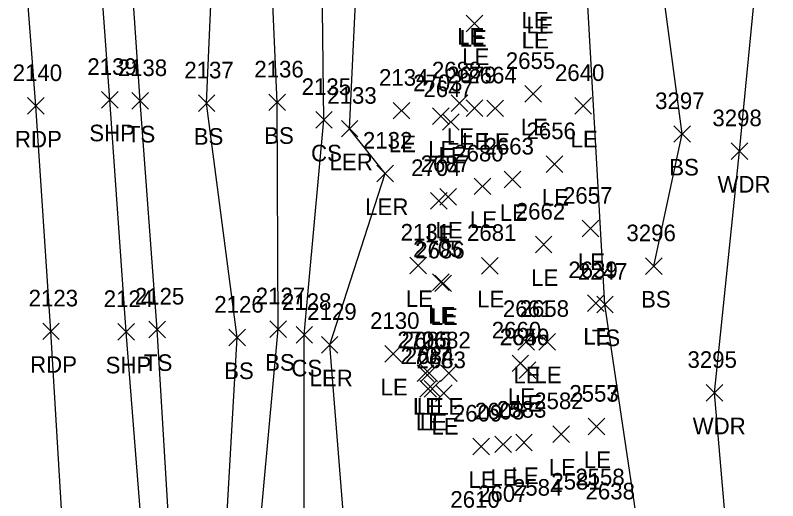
# Model space of a CAD drawing. Extents: x 1650221 to 1650634, y 244606 to 249996.
# Drawn here: x 1650384.9 to 1650476.7, y 246053.5 to 246112 of the extents above; entities that cross this region are included whole.
import ezdxf

# ---------------------------------------------------------------- set-up
doc = ezdxf.new("R2010")
doc.units = 0
for name, color, linetype in [('L_A', 7, 'Continuous'), ('L_I', 7, 'Continuous'), ('L_TIC', 7, 'Continuous'), ('LARO', 7, 'Continuous'), ('LAWA', 7, 'Continuous'), ('LELB', 7, 'Continuous'), ('P_A', 7, 'Continuous'), ('P_I', 7, 'Continuous'), ('P_TIC', 7, 'Continuous'), ('PET', 7, 'Continuous'), ('PSP', 7, 'Continuous')]:
    doc.layers.add(name, color=color, linetype=linetype)

msp = doc.modelspace()

# ---------------------------------------------------------------- linework, layer by layer
at = {"layer": 'L_TIC'}
for points in [[(1650439.182, 246110.018), (1650441.182, 246112.018)], [(1650441.182, 246110.018), (1650439.182, 246112.018)], [(1650446.244, 246101.548), (1650448.244, 246103.548)], [(1650448.244, 246101.548), (1650446.244, 246103.548)], [(1650398.903, 246100.695), (1650400.903, 246102.695)], [(1650400.903, 246100.695), (1650398.903, 246102.695)], [(1650406.916, 246100.417), (1650408.916, 246102.417)], [(1650408.916, 246100.417), (1650406.916, 246102.417)], [(1650415.402, 246100.528), (1650417.402, 246102.528)], [(1650417.402, 246100.528), (1650415.402, 246102.528)], [(1650437.343, 246100.414), (1650439.343, 246102.414)], [(1650439.343, 246100.414), (1650437.343, 246102.414)], [(1650430.36, 246099.524), (1650432.36, 246101.524)], [(1650432.36, 246099.524), (1650430.36, 246101.524)], [(1650439.182, 246099.825), (1650441.182, 246101.825)], [(1650441.182, 246099.825), (1650439.182, 246101.825)], [(1650441.655, 246099.809), (1650443.655, 246101.809)], [(1650443.655, 246099.809), (1650441.655, 246101.809)], [(1650452.248, 246100.099), (1650454.248, 246102.099)], [(1650454.248, 246100.099), (1650452.248, 246102.099)], [(1650435.108, 246098.873), (1650437.108, 246100.873)], [(1650437.108, 246098.873), (1650435.108, 246100.873)], [(1650421.044, 246098.416), (1650423.044, 246100.416)], [(1650423.044, 246098.416), (1650421.044, 246100.416)], [(1650436.325, 246098.162), (1650438.325, 246100.162)], [(1650438.325, 246098.162), (1650436.325, 246100.162)], [(1650424.132, 246097.356), (1650426.132, 246099.356)], [(1650426.132, 246097.356), (1650424.132, 246099.356)], [(1650464.176, 246096.717), (1650466.176, 246098.717)], [(1650466.176, 246096.717), (1650464.176, 246098.717)], [(1650471.068, 246094.652), (1650473.068, 246096.652)], [(1650473.068, 246094.652), (1650471.068, 246096.652)], [(1650448.788, 246093.093), (1650450.788, 246095.093)], [(1650450.788, 246093.093), (1650448.788, 246095.093)], [(1650428.423, 246091.952), (1650430.423, 246093.952)], [(1650430.423, 246091.952), (1650428.423, 246093.952)], [(1650443.726, 246091.241), (1650445.726, 246093.241)], [(1650445.726, 246091.241), (1650443.726, 246093.241)], [(1650440.113, 246090.409), (1650442.113, 246092.409)], [(1650442.113, 246090.409), (1650440.113, 246092.409)], [(1650434.876, 246088.657), (1650436.876, 246090.657)], [(1650436.876, 246088.657), (1650434.876, 246090.657)], [(1650435.987, 246089.132), (1650437.987, 246091.132)], [(1650437.987, 246089.132), (1650435.987, 246091.132)], [(1650453.126, 246085.32), (1650455.126, 246087.32)], [(1650455.126, 246085.32), (1650453.126, 246087.32)], [(1650447.491, 246083.404), (1650449.491, 246085.404)], [(1650449.491, 246083.404), (1650447.491, 246085.404)], [(1650432.398, 246080.878), (1650434.398, 246082.878)], [(1650434.398, 246080.878), (1650432.398, 246082.878)], [(1650441.004, 246080.832), (1650443.004, 246082.832)], [(1650443.004, 246080.832), (1650441.004, 246082.832)], [(1650460.775, 246080.801), (1650462.775, 246082.801)], [(1650462.775, 246080.801), (1650460.775, 246082.801)], [(1650435.112, 246078.875), (1650437.112, 246080.875)], [(1650437.112, 246078.875), (1650435.112, 246080.875)], [(1650435.394, 246078.725), (1650437.394, 246080.725)], [(1650437.394, 246078.725), (1650435.394, 246080.725)], [(1650453.777, 246076.349), (1650455.777, 246078.349)], [(1650455.777, 246076.349), (1650453.777, 246078.349)], [(1650454.878, 246076.164), (1650456.878, 246078.164)], [(1650456.878, 246076.164), (1650454.878, 246078.164)], [(1650400.961, 246073.172), (1650402.961, 246075.172)], [(1650402.961, 246073.172), (1650400.961, 246075.172)], [(1650415.512, 246073.201), (1650417.512, 246075.201)], [(1650417.512, 246073.201), (1650415.512, 246075.201)], [(1650410.581, 246072.193), (1650412.581, 246074.193)], [(1650412.581, 246072.193), (1650410.581, 246074.193)], [(1650418.673, 246072.519), (1650420.673, 246074.519)], [(1650420.673, 246072.519), (1650418.673, 246074.519)], [(1650421.728, 246071.324), (1650423.728, 246073.324)], [(1650423.728, 246071.324), (1650421.728, 246073.324)], [(1650445.372, 246071.673), (1650447.372, 246073.673)], [(1650447.372, 246071.673), (1650445.372, 246073.673)], [(1650447.905, 246071.689), (1650449.905, 246073.689)], [(1650449.905, 246071.689), (1650447.905, 246073.689)], [(1650429.37, 246070.233), (1650431.37, 246072.233)], [(1650431.37, 246070.233), (1650429.37, 246072.233)], [(1650444.681, 246069.088), (1650446.681, 246071.088)], [(1650446.681, 246069.088), (1650444.681, 246071.088)], [(1650433.266, 246067.911), (1650435.266, 246069.911)], [(1650435.266, 246067.911), (1650433.266, 246069.911)], [(1650433.721, 246067.893), (1650435.721, 246069.893)], [(1650435.721, 246067.893), (1650433.721, 246069.893)], [(1650436.071, 246067.895), (1650438.071, 246069.895)], [(1650438.071, 246067.895), (1650436.071, 246069.895)], [(1650445.553, 246068.271), (1650447.553, 246070.271)], [(1650447.553, 246068.271), (1650445.553, 246070.271)], [(1650445.555, 246068.273), (1650447.555, 246070.273)], [(1650447.555, 246068.273), (1650445.555, 246070.273)], [(1650433.599, 246066.011), (1650435.599, 246068.011)], [(1650435.599, 246066.011), (1650433.599, 246068.011)], [(1650434.088, 246066.012), (1650436.088, 246068.012)], [(1650436.088, 246066.012), (1650434.088, 246068.012)], [(1650468.072, 246065.542), (1650470.072, 246067.542)], [(1650470.072, 246065.542), (1650468.072, 246067.542)], [(1650435.488, 246065.506), (1650437.488, 246067.506)], [(1650437.488, 246065.506), (1650435.488, 246067.506)], [(1650453.841, 246061.471), (1650455.841, 246063.471)], [(1650455.841, 246061.471), (1650453.841, 246063.471)], [(1650453.845, 246061.472), (1650455.845, 246063.472)], [(1650455.845, 246061.472), (1650453.845, 246063.472)], [(1650449.611, 246060.571), (1650451.611, 246062.571)], [(1650451.611, 246060.571), (1650449.611, 246062.571)], [(1650442.604, 246059.334), (1650444.604, 246061.334)], [(1650444.604, 246059.334), (1650442.604, 246061.334)], [(1650445.129, 246059.542), (1650447.129, 246061.542)], [(1650447.129, 246059.542), (1650445.129, 246061.542)], [(1650439.96, 246059.078), (1650441.96, 246061.078)], [(1650441.96, 246059.078), (1650439.96, 246061.078)]]:
    msp.add_lwpolyline(points, dxfattribs=at)
at = {"layer": 'LARO'}
msp.add_lwpolyline([(1650458.351, 245631.93), (1650449.504, 245684.326), (1650450.495, 245714.604), (1650445.163, 245758.174), (1650441.43, 245763.318), (1650445.691, 245790.789), (1650445.259, 245833.565), (1650436.072, 245846.145), (1650437.664, 245854.857), (1650443.78, 245871.9), (1650444.436, 245931.496), (1650440.464, 245954.233), (1650431.438, 245970.003), (1650423.576, 246015.539), (1650425.235, 246041.195), (1650422.728, 246072.324), (1650429.423, 246092.952), (1650425.132, 246098.356), (1650427.506, 246149.078), (1650414.343, 246173.263), (1650408.62, 246217.57), (1650415.017, 246258.551)], dxfattribs=at)
at = {"layer": 'LAWA'}
msp.add_lwpolyline([(1650483.506, 245961.471), (1650475.645, 245986.689), (1650473.947, 246015.709), (1650470.996, 246044.201), (1650469.072, 246066.542), (1650472.068, 246095.652), (1650474.903, 246124.519), (1650465.874, 246151.643), (1650463.487, 246169.043), (1650462.419, 246192.613), (1650462.694, 246202.486), (1650464.837, 246226.502), (1650467.45, 246241.248), (1650457.439, 246253.738)], dxfattribs=at)
at = {"layer": 'LELB'}
for points in [[(1650490.897, 245637.991), (1650484.147, 245671.673), (1650476.863, 245685.264), (1650481.343, 245732.022), (1650469.963, 245747.747), (1650469.909, 245798.43), (1650476.133, 245853.709), (1650478.543, 245903.037), (1650467.895, 245956.036), (1650466.732, 245989.258), (1650461.997, 246035.907), (1650455.878, 246077.164), (1650453.103, 246125.912), (1650454.427, 246141.055), (1650448.02, 246165.285), (1650445.175, 246217.398), (1650445.531, 246269.295)], [(1650438.583, 245683.7), (1650437.216, 245716.147), (1650434.989, 245762.368), (1650435.617, 245791.449), (1650430.688, 245841.825), (1650429.64, 245875.078), (1650426.153, 245928.206), (1650418.701, 245970.613), (1650416.699, 246015.219), (1650413.61, 246042.182), (1650416.512, 246074.201), (1650416.402, 246101.528), (1650414.29, 246149.926), (1650404.833, 246174.668), (1650402.25, 246216.694), (1650398.468, 246258.758)], [(1650434.287, 245631.651), (1650429.679, 245683.37), (1650427.7, 245716.211), (1650423.737, 245761.411), (1650422.945, 245791.623), (1650419.788, 245841.038), (1650417.748, 245874.985), (1650413.207, 245925.882), (1650409.303, 245969.616), (1650405.703, 246013.514), (1650403.9, 246042.148), (1650401.961, 246074.172), (1650399.903, 246101.695), (1650397.072, 246143.432), (1650394.377, 246175.594), (1650393.271, 246215.062), (1650388.589, 246258.034)], [(1650442.322, 245632.051), (1650435.429, 245684.425), (1650431.919, 245716.003), (1650428.741, 245761.443), (1650429.827, 245791.581), (1650424.827, 245840.768), (1650421.853, 245874.713), (1650419.56, 245927.21), (1650413.673, 245970.026), (1650411.821, 246014.765), (1650409.818, 246042.312), (1650411.581, 246073.193), (1650407.916, 246101.417), (1650409.975, 246148.815), (1650401.746, 246175.353), (1650398.424, 246215.354), (1650393.502, 246258.252)], [(1650450.462, 245632.254), (1650446.794, 245683.077), (1650444.968, 245714.813), (1650439.754, 245763.702), (1650441.247, 245791.527), (1650434.825, 245844.514), (1650438.485, 245872.14), (1650441.087, 245931.175), (1650427.554, 245969.423), (1650420.965, 246016.018), (1650419.637, 246042.015), (1650419.673, 246073.519), (1650422.044, 246099.416), (1650421.428, 246149.379), (1650410.206, 246173.05), (1650406.656, 246218.25), (1650409.738, 246258.013)], [(1650461.775, 246081.801), (1650465.176, 246097.717), (1650460.579, 246132.026), (1650462.244, 246139.337), (1650465.874, 246151.643), (1650477.029, 246147.805), (1650492.828, 246151.916), (1650506.898, 246166.648)]]:
    msp.add_lwpolyline(points, dxfattribs=at)
at = {"layer": 'P_TIC'}
for points in [[(1650395.249, 246100.835), (1650397.249, 246102.835)], [(1650397.249, 246100.835), (1650395.249, 246102.835)], [(1650386.342, 246100.094), (1650388.342, 246102.094)], [(1650388.342, 246100.094), (1650386.342, 246102.094)], [(1650388.172, 246072.947), (1650390.172, 246074.947)], [(1650390.172, 246072.947), (1650388.172, 246074.947)], [(1650397.212, 246072.878), (1650399.212, 246074.878)], [(1650399.212, 246072.878), (1650397.212, 246074.878)]]:
    msp.add_lwpolyline(points, dxfattribs=at)
at = {"layer": 'PET'}
msp.add_lwpolyline([(1650421.181, 245630.653), (1650417.911, 245681.781), (1650415.194, 245715.716), (1650411.644, 245760.213), (1650409.56, 245790.153), (1650405.955, 245839.71), (1650403.344, 245877.001), (1650399.576, 245923.323), (1650396.218, 245968.531), (1650393.167, 246011.847), (1650391.121, 246041.148), (1650389.172, 246073.947), (1650387.342, 246101.094), (1650384.18, 246142.539), (1650381.858, 246175.149), (1650378.627, 246214.911), (1650375.804, 246256.561)], dxfattribs=at)
at = {"layer": 'PSP'}
msp.add_lwpolyline([(1650430.245, 245631.195), (1650426.212, 245683.008), (1650424.031, 245715.851), (1650420.575, 245760.812), (1650418.536, 245792.05), (1650414.923, 245840.836), (1650412.563, 245876.113), (1650408.949, 245925.602), (1650405.846, 245970.072), (1650402.84, 246013.322), (1650400.757, 246041.785), (1650398.212, 246073.878), (1650396.249, 246101.835), (1650393.23, 246143.038), (1650390.863, 246175.906), (1650388.25, 246215.072), (1650385.023, 246257.594)], dxfattribs=at)

# ---------------------------------------------------------------- texts
at = {"layer": 'L_A'}
for s, p in [('LE', (1650445.814, 246110.429)), ('LE', (1650446.41, 246109.831)), ('LE', (1650438.075, 246108.48)), ('LE', (1650438.373, 246108.242)), ('LE', (1650445.843, 246108.02)), ('LE', (1650438.67, 246106.018)), ('LE', (1650445.732, 246097.548)), ('TS', (1650398.312, 246096.695)), ('BS', (1650406.357, 246096.417)), ('BS', (1650414.843, 246096.528)), ('LE', (1650436.832, 246096.414)), ('LE', (1650438.67, 246095.825)), ('LE', (1650451.736, 246096.099)), ('LE', (1650429.849, 246095.524)), ('LE', (1650441.143, 246095.809)), ('CS', (1650420.485, 246094.416)), ('LE', (1650434.596, 246094.873)), ('LE', (1650435.814, 246094.162)), ('LER', (1650422.715, 246093.356)), ('BS', (1650463.617, 246092.717)), ('WDR', (1650469.431, 246090.652)), ('LE', (1650448.276, 246089.093)), ('LER', (1650427.005, 246087.952)), ('LE', (1650443.214, 246087.241)), ('LE', (1650439.602, 246086.409)), ('LE', (1650435.475, 246085.132)), ('LE', (1650434.364, 246084.657)), ('LE', (1650452.614, 246081.32)), ('LE', (1650446.979, 246079.404)), ('LE', (1650431.886, 246076.878)), ('LE', (1650440.492, 246076.832)), ('BS', (1650460.216, 246076.801)), ('LE', (1650434.6, 246074.875)), ('LE', (1650434.882, 246074.725)), ('LE', (1650453.265, 246072.349)), ('TS', (1650454.287, 246072.164)), ('TS', (1650400.37, 246069.172)), ('BS', (1650414.953, 246069.201)), ('CS', (1650418.114, 246068.519)), ('BS', (1650410.022, 246068.193)), ('LE', (1650444.861, 246067.673)), ('LE', (1650447.393, 246067.689)), ('LER', (1650420.311, 246067.324)), ('LE', (1650428.858, 246066.233)), ('LE', (1650444.17, 246065.088)), ('LE', (1650432.754, 246063.911)), ('LE', (1650433.209, 246063.893)), ('LE', (1650435.559, 246063.895)), ('LE', (1650445.042, 246064.271)), ('LE', (1650445.044, 246064.273)), ('LE', (1650433.087, 246062.011)), ('LE', (1650433.576, 246062.012)), ('LE', (1650434.976, 246061.506)), ('WDR', (1650466.435, 246061.542)), ('LE', (1650453.33, 246057.471)), ('LE', (1650453.333, 246057.472)), ('LE', (1650449.1, 246056.571)), ('LE', (1650444.618, 246055.542)), ('LE', (1650439.448, 246055.078)), ('LE', (1650442.092, 246055.334))]:
    msp.add_text(s, height=2, dxfattribs=at).set_placement(p)
at = {"layer": 'L_I'}
for s, p in [('2655', (1650443.937, 246105.548)), ('2138', (1650397.21, 246104.695)), ('2137', (1650405.223, 246104.417)), ('2136', (1650413.654, 246104.528)), ('2688', (1650435.036, 246104.414)), ('2640', (1650449.854, 246104.099)), ('2134', (1650428.667, 246103.524)), ('2679', (1650436.867, 246103.825)), ('2664', (1650439.301, 246103.809)), ('2135', (1650419.351, 246102.416)), ('2703', (1650432.769, 246102.873)), ('2133', (1650422.439, 246101.356)), ('2647', (1650434.018, 246102.162)), ('3297', (1650461.916, 246100.717)), ('3298', (1650468.809, 246098.652)), ('2656', (1650446.426, 246097.093)), ('2132', (1650426.73, 246095.952)), ('2663', (1650441.371, 246095.241)), ('2680', (1650437.72, 246094.409)), ('2687', (1650433.68, 246093.132)), ('2704', (1650432.537, 246092.657)), ('2657', (1650450.819, 246089.32)), ('2662', (1650445.137, 246087.404)), ('2131', (1650431.272, 246084.878)), ('2681', (1650439.264, 246084.832)), ('3296', (1650458.46, 246084.801)), ('2705', (1650432.773, 246082.875)), ('2686', (1650433.032, 246082.725)), ('2639', (1650451.462, 246080.349)), ('2247', (1650452.618, 246080.164)), ('2125', (1650399.268, 246077.172)), ('2127', (1650413.819, 246077.201)), ('2128', (1650416.98, 246076.519)), ('2126', (1650408.833, 246076.193)), ('2661', (1650443.585, 246075.673)), ('2658', (1650445.598, 246075.689)), ('2129', (1650420.028, 246075.324)), ('2130', (1650427.59, 246074.233)), ('2660', (1650442.24, 246073.088)), ('2646', (1650443.191, 246072.271)), ('2659', (1650443.24, 246072.273)), ('2706', (1650430.872, 246071.911)), ('2685', (1650431.414, 246071.893)), ('2682', (1650433.764, 246071.895)), ('2707', (1650431.26, 246070.011)), ('2684', (1650431.781, 246070.012)), ('2683', (1650433.181, 246069.506)), ('3295', (1650465.813, 246069.542)), ('2553', (1650451.582, 246065.471)), ('2557', (1650451.585, 246065.472)), ('2582', (1650447.352, 246064.571)), ('2609', (1650437.566, 246063.078)), ('2608', (1650440.218, 246063.334)), ('2583', (1650442.87, 246063.542)), ('2558', (1650452.298, 246055.398)), ('2581', (1650449.421, 246054.876)), ('2584', (1650444.793, 246054.147)), ('2638', (1650453.534, 246053.7)), ('2610', (1650437.258, 246052.696)), ('2607', (1650440.601, 246053.401))]:
    msp.add_text(s, height=2, dxfattribs=at).set_placement(p)
at = {"layer": 'P_A'}
for s, p in [('SHP', (1650393.784, 246096.835)), ('RDP', (1650384.83, 246096.094)), ('RDP', (1650386.66, 246068.947)), ('SHP', (1650395.748, 246068.878))]:
    msp.add_text(s, height=2, dxfattribs=at).set_placement(p)
at = {"layer": 'P_I'}
for s, p in [('2140', (1650384.562, 246104.094)), ('2139', (1650393.548, 246104.835)), ('2123', (1650386.479, 246076.947)), ('2124', (1650395.519, 246076.878))]:
    msp.add_text(s, height=2, dxfattribs=at).set_placement(p)

doc.saveas('drawing.dxf')
